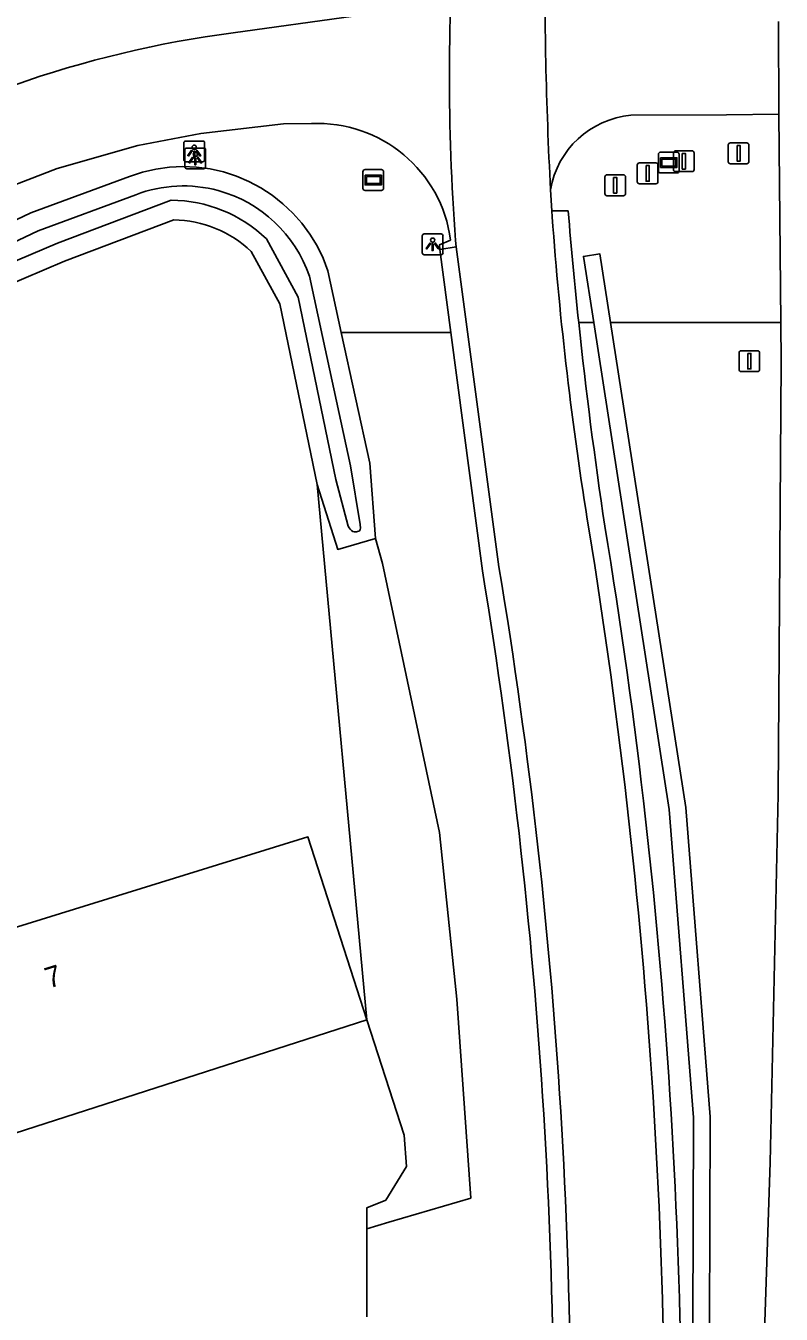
# Model space of a CAD drawing. Extents: x 161389 to 162585, y 388479 to 389761.
# Drawn here: x 162549.2 to 162585.4, y 389564.4 to 389626.2 of the extents above; entities that cross this region are included whole.
import ezdxf

# ---------------------------------------------------------------- set-up
doc = ezdxf.new("R2010")
doc.units = 0
for name, color, linetype in [('IMGEO_Afsluitpaal', 7, 'Continuous'), ('IMGEO_Berm_groen', 7, 'Continuous'), ('IMGEO_Berm_open', 7, 'Continuous'), ('IMGEO_Erf', 7, 'Continuous'), ('IMGEO_Fietspad_gesloten', 7, 'Continuous'), ('IMGEO_Grasland_overig', 7, 'Continuous'), ('IMGEO_Groenvoorziening', 7, 'Continuous'), ('IMGEO_Haag', 7, 'Continuous'), ('IMGEO_Hek', 7, 'Continuous'), ('IMGEO_Lichtpunt', 7, 'Continuous'), ('IMGEO_Pand', 7, 'Continuous'), ('IMGEO_Pand_nummerreeks', 7, 'Continuous'), ('IMGEO_Rijbaan_lokaal_open', 7, 'Continuous'), ('IMGEO_Rijbaan_regionaal_gesloten', 7, 'Continuous'), ('IMGEO_Straatnaambord', 7, 'Continuous'), ('IMGEO_Verkeersbordpaal', 7, 'Continuous'), ('IMGEO_Waterloop', 7, 'Continuous')]:
    doc.layers.add(name, color=color, linetype=linetype)

msp = doc.modelspace()

# ---------------------------------------------------------------- linework, layer by layer
at = {"layer": 'IMGEO_Afsluitpaal'}
for p, q in [((162580.229, 389619.286), (162580.229, 389620.086)), ((162580.229, 389620.086), (162580.229, 389619.286)), ((162580.329, 389620.186), (162581.119, 389620.186)), ((162581.119, 389620.186), (162580.329, 389620.186)), ((162581.219, 389620.086), (162581.219, 389619.286)), ((162581.219, 389619.286), (162581.219, 389620.086)), ((162578.495, 389618.704), (162578.495, 389619.504)), ((162578.495, 389619.504), (162578.495, 389618.704)), ((162578.595, 389619.604), (162579.385, 389619.604)), ((162579.385, 389619.604), (162578.595, 389619.604)), ((162579.485, 389619.504), (162579.485, 389618.704)), ((162579.485, 389618.704), (162579.485, 389619.504)), ((162576.939, 389618.134), (162576.939, 389618.934)), ((162576.939, 389618.934), (162576.939, 389618.134)), ((162577.039, 389619.034), (162577.829, 389619.034)), ((162577.829, 389619.034), (162577.039, 389619.034)), ((162577.929, 389618.934), (162577.929, 389618.134)), ((162577.929, 389618.134), (162577.929, 389618.934)), ((162581.119, 389619.186), (162580.329, 389619.186)), ((162580.329, 389619.186), (162581.119, 389619.186)), ((162579.385, 389618.604), (162578.595, 389618.604)), ((162578.595, 389618.604), (162579.385, 389618.604)), ((162577.829, 389618.034), (162577.039, 389618.034)), ((162577.039, 389618.034), (162577.829, 389618.034))]:
    msp.add_line(p, q, dxfattribs=at)
for points in [[(162580.649, 389620.061), (162580.799, 389620.061), (162580.799, 389619.311), (162580.649, 389619.311), (162580.649, 389620.061)], [(162578.915, 389619.479), (162579.065, 389619.479), (162579.065, 389618.729), (162578.915, 389618.729), (162578.915, 389619.479)], [(162577.359, 389618.909), (162577.509, 389618.909), (162577.509, 389618.159), (162577.359, 389618.159), (162577.359, 389618.909)]]:
    msp.add_lwpolyline(points, dxfattribs=at)
for centre, start, end in [((162580.329, 389620.086), 90, 180), ((162580.329, 389620.086), 90, 180), ((162581.119, 389620.086), 0, 90), ((162581.119, 389620.086), 360, 90), ((162578.595, 389619.504), 90, 180), ((162578.595, 389619.504), 90, 180), ((162579.385, 389619.504), 0, 90), ((162579.385, 389619.504), 360, 90), ((162577.039, 389618.934), 90, 180), ((162577.039, 389618.934), 90, 180), ((162577.829, 389618.934), 0, 90), ((162577.829, 389618.934), 360, 90), ((162580.329, 389619.286), 180, 270), ((162580.329, 389619.286), 180, 270), ((162581.119, 389619.286), 270, 0), ((162581.119, 389619.286), 270, 0), ((162577.039, 389618.134), 180, 270), ((162577.039, 389618.134), 180, 270), ((162577.829, 389618.134), 270, 0), ((162577.829, 389618.134), 270, 0), ((162578.595, 389618.704), 180, 270), ((162578.595, 389618.704), 180, 270), ((162579.385, 389618.704), 270, 0), ((162579.385, 389618.704), 270, 0)]:
    msp.add_arc(centre, 0.1, start, end, dxfattribs=at)
at = {"layer": 'IMGEO_Berm_groen'}
for points in [[(162575.683, 389611.948), (162576.401, 389611.948)], [(162585.381, 389611.948), (162577.211, 389611.948)]]:
    msp.add_lwpolyline(points, dxfattribs=at)
at = {"layer": 'IMGEO_Berm_open'}
for points in [[(162575.179, 389617.305), (162574.394, 389617.306)], [(162569.542, 389611.473), (162569.012, 389615.454)], [(162569.542, 389611.473), (162571.066, 389600.036)]]:
    msp.add_lwpolyline(points, dxfattribs=at)
for centre, radius, start, end in [((162799.629, 389635.72), 225.204, 184.69023, 186.05919), ((162797.305, 389635.461), 222.866, 186.05613, 188.58795), ((162304.581, 389557.197), 276.047, 357.60133, 9.37857), ((162316.554, 389558.165), 257.933, 357.30505, 9.3424)]:
    msp.add_arc(centre, radius, start, end, dxfattribs=at)
at = {"layer": 'IMGEO_Erf'}
for points in [[(162556.26, 389616.875), (162551.015, 389614.89), (162542.21, 389611.153)], [(162563.127, 389604.182), (162561.337, 389612.849), (162559.973, 389615.358)]]:
    msp.add_lwpolyline(points, dxfattribs=at)
msp.add_arc((162556.168, 389611.346), 5.529, 46.51088, 89.04276, dxfattribs=at)
at = {"layer": 'IMGEO_Fietspad_gesloten'}
for points in [[(162574.394, 389617.306), (162574.33, 389618.32)], [(162574.412, 389617.022), (162574.394, 389617.306)], [(162569.81, 389615.58), (162571.853, 389600.234)]]:
    msp.add_lwpolyline(points, dxfattribs=at)
for centre, radius, start, end in [((162741.687, 389629.076), 167.709, 184.1217, 189.27533), ((162298.657, 389556.881), 281.165, 357.71269, 9.24346), ((162320.629, 389558.476), 254.671, 357.21462, 9.43739)]:
    msp.add_arc(centre, radius, start, end, dxfattribs=at)
at = {"layer": 'IMGEO_Grasland_overig'}
for points in [[(162565.517, 389578.496), (162563.127, 389604.182)], [(162563.127, 389604.182), (162564.12, 389601.066), (162565.932, 389601.592)], [(162565.511, 389568.468), (162566.568, 389568.781), (162570.503, 389569.945), (162569.833, 389579.478), (162569.005, 389587.486), (162566.274, 389600.392), (162565.932, 389601.592)], [(162565.511, 389568.468), (162565.512, 389569.468), (162566.425, 389569.847), (162567.427, 389571.463), (162567.301, 389572.963), (162565.517, 389578.496)]]:
    msp.add_lwpolyline(points, dxfattribs=at)
at = {"layer": 'IMGEO_Groenvoorziening'}
for points in [[(162544.825, 389615.043), (162549.393, 389617.208), (162554.136, 389618.956), (162554.76, 389619.16), (162555.397, 389619.307), (162556.044, 389619.396), (162556.696, 389619.427), (162557.349, 389619.4), (162557.996, 389619.315), (162558.634, 389619.172), (162559.256, 389618.972), (162559.857, 389618.718), (162560.434, 389618.412), (162560.981, 389618.054), (162561.494, 389617.65), (162561.968, 389617.201), (162562.401, 389616.712), (162562.788, 389616.186), (162563.127, 389615.627), (162563.414, 389615.041), (162563.648, 389614.431), (162564.291, 389611.473)], [(162564.291, 389611.473), (162569.542, 389611.473)], [(162565.932, 389601.592), (162565.655, 389605.204), (162564.291, 389611.473)], [(162565.509, 389564.253), (162565.511, 389568.468)]]:
    msp.add_lwpolyline(points, dxfattribs=at)
at = {"layer": 'IMGEO_Haag'}
for points in [[(162577.211, 389611.948), (162576.7, 389615.241), (162575.91, 389615.119), (162576.401, 389611.948)], [(162576.401, 389611.948), (162580.024, 389588.585), (162581.189, 389573.807), (162581.108, 389548.906), (162580.883, 389537.221), (162580.277, 389524.986), (162575.533, 389457.902), (162574.175, 389443.824), (162572.862, 389427.679), (162570.704, 389413.369), (162566.096, 389385.679), (162560.933, 389354.655), (162556.805, 389331.01), (162550.72, 389299.239), (162545.517, 389273.568), (162541.107, 389250.072), (162537.047, 389227.348), (162534.227, 389211.564), (162530.189, 389185.447), (162527.69, 389164.49), (162526.335, 389154.682), (162524.353, 389145.747), (162522.076, 389137.161), (162518.583, 389120.758)], [(162566.887, 389385.563), (162571.494, 389413.243), (162573.654, 389427.569), (162574.974, 389443.664), (162576.412, 389457.802), (162581.075, 389524.942), (162581.683, 389537.193), (162581.908, 389548.898), (162581.989, 389573.837), (162580.82, 389588.677), (162577.211, 389611.948)]]:
    msp.add_lwpolyline(points, dxfattribs=at)
at = {"layer": 'IMGEO_Hek'}
msp.add_lwpolyline([(162565.932, 389601.592), (162566.274, 389600.392), (162569.005, 389587.486), (162569.833, 389579.478), (162570.503, 389569.945), (162566.568, 389568.781), (162565.511, 389568.468)], dxfattribs=at)
at = {"layer": 'IMGEO_Lichtpunt'}
for p, q in [((162557.637, 389620.655), (162556.829, 389620.655)), ((162557.637, 389620.655), (162556.829, 389620.655)), ((162556.735, 389620.56), (162556.735, 389619.753)), ((162556.735, 389620.56), (162556.735, 389619.753)), ((162556.785, 389620.224), (162556.785, 389619.417)), ((162556.785, 389620.224), (162556.785, 389619.417)), ((162557.687, 389620.319), (162556.879, 389620.319)), ((162557.687, 389620.319), (162556.879, 389620.319)), ((162557.731, 389619.753), (162557.731, 389620.56)), ((162557.731, 389619.753), (162557.731, 389620.56)), ((162557.781, 389619.417), (162557.781, 389620.224)), ((162557.781, 389619.417), (162557.781, 389620.224)), ((162556.829, 389619.659), (162557.637, 389619.659)), ((162556.829, 389619.659), (162557.637, 389619.659)), ((162556.879, 389619.323), (162557.687, 389619.323)), ((162556.879, 389619.323), (162557.687, 389619.323)), ((162568.175, 389616.104), (162568.175, 389615.297)), ((162568.175, 389616.104), (162568.175, 389615.297)), ((162569.077, 389616.199), (162568.269, 389616.199)), ((162569.077, 389616.199), (162568.269, 389616.199)), ((162569.171, 389615.297), (162569.171, 389616.104)), ((162569.171, 389615.297), (162569.171, 389616.104)), ((162568.269, 389615.203), (162569.077, 389615.203)), ((162568.269, 389615.203), (162569.077, 389615.203))]:
    msp.add_line(p, q, dxfattribs=at)
for points in [[(162557.109, 389620.224), (162557.148, 389620.196), (162556.96, 389619.934), (162556.922, 389619.961), (162557.109, 389620.224)], [(162557.211, 389620.176), (162557.258, 389620.176), (162557.258, 389619.854), (162557.211, 389619.854), (162557.211, 389620.176)], [(162557.321, 389620.196), (162557.359, 389620.223), (162557.546, 389619.961), (162557.507, 389619.933), (162557.321, 389620.196)], [(162557.159, 389619.888), (162557.198, 389619.86), (162557.01, 389619.598), (162556.972, 389619.625), (162557.159, 389619.888)], [(162557.261, 389619.84), (162557.308, 389619.84), (162557.308, 389619.518), (162557.261, 389619.518), (162557.261, 389619.84)], [(162557.371, 389619.86), (162557.409, 389619.887), (162557.596, 389619.625), (162557.557, 389619.597), (162557.371, 389619.86)], [(162568.549, 389615.768), (162568.588, 389615.74), (162568.4, 389615.478), (162568.362, 389615.505), (162568.549, 389615.768)], [(162568.651, 389615.72), (162568.698, 389615.72), (162568.698, 389615.398), (162568.651, 389615.398), (162568.651, 389615.72)], [(162568.761, 389615.74), (162568.799, 389615.767), (162568.986, 389615.505), (162568.947, 389615.477), (162568.761, 389615.74)]]:
    msp.add_lwpolyline(points, dxfattribs=at)
for centre in [(162557.234, 389620.358), (162557.284, 389620.022), (162568.674, 389615.902)]:
    msp.add_circle(centre, 0.0994, dxfattribs=at)
for centre, start, end in [((162556.829, 389620.56), 90, 180), ((162556.829, 389620.56), 90, 180), ((162557.637, 389620.56), 0, 90), ((162557.637, 389620.56), 0, 90), ((162556.879, 389620.224), 90, 180), ((162556.879, 389620.224), 90, 180), ((162557.687, 389620.224), 0, 90), ((162557.687, 389620.224), 0, 90), ((162556.829, 389619.753), 180, 270), ((162556.829, 389619.753), 180, 270), ((162556.879, 389619.417), 180, 270), ((162556.879, 389619.417), 180, 270), ((162557.637, 389619.753), 270, 0), ((162557.637, 389619.753), 270, 360), ((162557.687, 389619.417), 270, 0), ((162557.687, 389619.417), 270, 360), ((162568.269, 389616.104), 90, 180), ((162568.269, 389616.104), 90, 180), ((162569.077, 389616.104), 0, 90), ((162569.077, 389616.104), 0, 90), ((162568.269, 389615.297), 180, 270), ((162568.269, 389615.297), 180, 270), ((162569.077, 389615.297), 270, 0), ((162569.077, 389615.297), 270, 360)]:
    msp.add_arc(centre, 0.0946, start, end, dxfattribs=at)
at = {"layer": 'IMGEO_Pand'}
msp.add_lwpolyline([(162565.517, 389578.496), (162547.191, 389572.588), (162548.561, 389568.331), (162543.802, 389566.8), (162536.446, 389564.434), (162534.742, 389569.151), (162534.484, 389569.057), (162531.437, 389577.419), (162530.514, 389577.136), (162528.223, 389583.678), (162526.571, 389588.397), (162532.896, 389590.432), (162536.408, 389579.136), (162562.687, 389587.272), (162565.517, 389578.496)], dxfattribs=at)
at = {"layer": 'IMGEO_Rijbaan_lokaal_open'}
for points in [[(162564.872, 389626.65), (162559.11, 389625.846)], [(162585.282, 389621.948), (162582.777, 389621.907), (162578.187, 389621.891)], [(162540.808, 389614.65), (162543.297, 389616.119), (162546.908, 389617.892), (162550.663, 389619.336), (162554.532, 389620.438), (162557.552, 389621.024), (162561.524, 389621.473), (162562.854, 389621.493)], [(162569.536, 389615.902), (162569.005, 389615.679), (162569.012, 389615.454)], [(162569.777, 389615.884), (162569.81, 389615.58)], [(162569.012, 389615.454), (162569.81, 389615.58)]]:
    msp.add_lwpolyline(points, dxfattribs=at)
for centre, radius, start, end in [((162673.78, 389623.757), 104.3, 175.42344, 184.32891), ((162779.561, 389628.973), 205.507, 179.55092, 182.97148), ((162565.779, 389574.575), 51.702, 97.41083, 121.50429), ((162578.587, 389617.591), 4.319, 95.31281, 170.27725), ((162563.15, 389615.058), 6.442, 7.52759, 92.63225)]:
    msp.add_arc(centre, radius, start, end, dxfattribs=at)
at = {"layer": 'IMGEO_Rijbaan_regionaal_gesloten'}
for points in [[(162585.265, 389626.39), (162585.282, 389621.948)], [(162585.282, 389621.948), (162585.381, 389611.948)], [(162585.381, 389611.948), (162585.4, 389610.051), (162585.248, 389589.308), (162584.865, 389571.651), (162583.796, 389539.634), (162581.454, 389500), (162580.161, 389481.84), (162577.531, 389457.924), (162576.279, 389443.681), (162572.42, 389412.852), (162568.516, 389385.324)]]:
    msp.add_lwpolyline(points, dxfattribs=at)
at = {"layer": 'IMGEO_Straatnaambord'}
for p, q in [((162579.507, 389619.223), (162579.507, 389620.023)), ((162579.507, 389620.023), (162579.507, 389619.223)), ((162579.607, 389620.123), (162580.397, 389620.123)), ((162580.397, 389620.123), (162579.607, 389620.123)), ((162580.497, 389620.023), (162580.497, 389619.223)), ((162580.497, 389619.223), (162580.497, 389620.023)), ((162565.331, 389618.384), (162565.331, 389619.184)), ((162565.331, 389619.184), (162565.331, 389618.384)), ((162565.431, 389619.284), (162566.221, 389619.284)), ((162566.221, 389619.284), (162565.431, 389619.284)), ((162566.321, 389619.184), (162566.321, 389618.384)), ((162566.321, 389618.384), (162566.321, 389619.184)), ((162580.397, 389619.123), (162579.607, 389619.123)), ((162579.607, 389619.123), (162580.397, 389619.123)), ((162566.221, 389618.284), (162565.431, 389618.284)), ((162565.431, 389618.284), (162566.221, 389618.284))]:
    msp.add_line(p, q, dxfattribs=at)
for points in [[(162579.608, 389619.855), (162580.396, 389619.855), (162580.396, 389619.391), (162579.608, 389619.391), (162579.608, 389619.855)], [(162579.673, 389619.79), (162579.673, 389619.456), (162580.331, 389619.456), (162580.331, 389619.79), (162579.673, 389619.79)], [(162565.432, 389619.016), (162566.22, 389619.016), (162566.22, 389618.552), (162565.432, 389618.552), (162565.432, 389619.016)], [(162565.497, 389618.951), (162565.497, 389618.617), (162566.155, 389618.617), (162566.155, 389618.951), (162565.497, 389618.951)]]:
    msp.add_lwpolyline(points, dxfattribs=at)
for centre, start, end in [((162579.607, 389620.023), 90, 180), ((162579.607, 389620.023), 90, 180), ((162580.397, 389620.023), 0, 90), ((162580.397, 389620.023), 360, 90), ((162565.431, 389619.184), 90, 180), ((162565.431, 389619.184), 90, 180), ((162566.221, 389619.184), 0, 90), ((162566.221, 389619.184), 360, 90), ((162579.607, 389619.223), 180, 270), ((162579.607, 389619.223), 180, 270), ((162580.397, 389619.223), 270, 0), ((162580.397, 389619.223), 270, 0), ((162565.431, 389618.384), 180, 270), ((162565.431, 389618.384), 180, 270), ((162566.221, 389618.384), 270, 0), ((162566.221, 389618.384), 270, 0)]:
    msp.add_arc(centre, 0.1, start, end, dxfattribs=at)
at = {"layer": 'IMGEO_Verkeersbordpaal'}
for p, q in [((162582.96, 389620.565), (162583.75, 389620.565)), ((162583.75, 389620.565), (162582.96, 389620.565)), ((162582.86, 389619.665), (162582.86, 389620.465)), ((162582.86, 389620.465), (162582.86, 389619.665)), ((162583.85, 389620.465), (162583.85, 389619.665)), ((162583.85, 389619.665), (162583.85, 389620.465)), ((162583.75, 389619.565), (162582.96, 389619.565)), ((162582.96, 389619.565), (162583.75, 389619.565)), ((162583.374, 389609.694), (162583.374, 389610.494)), ((162583.374, 389610.494), (162583.374, 389609.694)), ((162583.474, 389610.594), (162584.264, 389610.594)), ((162584.264, 389610.594), (162583.474, 389610.594)), ((162584.364, 389610.494), (162584.364, 389609.694)), ((162584.364, 389609.694), (162584.364, 389610.494)), ((162584.264, 389609.594), (162583.474, 389609.594)), ((162583.474, 389609.594), (162584.264, 389609.594))]:
    msp.add_line(p, q, dxfattribs=at)
for points in [[(162583.28, 389620.44), (162583.43, 389620.44), (162583.43, 389619.69), (162583.28, 389619.69), (162583.28, 389620.44)], [(162583.794, 389610.469), (162583.944, 389610.469), (162583.944, 389609.719), (162583.794, 389609.719), (162583.794, 389610.469)]]:
    msp.add_lwpolyline(points, dxfattribs=at)
for centre, start, end in [((162582.96, 389620.465), 90, 180), ((162582.96, 389620.465), 90, 180), ((162583.75, 389620.465), 0, 90), ((162583.75, 389620.465), 360, 90), ((162582.96, 389619.665), 180, 270), ((162582.96, 389619.665), 180, 270), ((162583.75, 389619.665), 270, 0), ((162583.75, 389619.665), 270, 0), ((162583.474, 389610.494), 90, 180), ((162583.474, 389610.494), 90, 180), ((162584.264, 389610.494), 0, 90), ((162584.264, 389610.494), 360, 90), ((162583.474, 389609.694), 180, 270), ((162583.474, 389609.694), 180, 270), ((162584.264, 389609.694), 270, 0), ((162584.264, 389609.694), 270, 0)]:
    msp.add_arc(centre, 0.1, start, end, dxfattribs=at)
at = {"layer": 'IMGEO_Waterloop'}
for points in [[(162542.564, 389612.602), (162542.645, 389612.71), (162545.256, 389614.223), (162549.752, 389616.354), (162554.44, 389618.082)], [(162556.132, 389617.816), (162550.67, 389615.749), (162542.877, 389612.441)], [(162564.62, 389602.181), (162564.023, 389604.417), (162562.215, 389613.17), (162560.699, 389615.96)], [(162562.759, 389614.166), (162563.387, 389611.276), (162564.737, 389605.07), (162565.197, 389602.257), (162565.21, 389602.084)], [(162565.075, 389601.915), (162565.019, 389601.908), (162564.906, 389601.91), (162564.852, 389601.925)]]:
    msp.add_lwpolyline(points, dxfattribs=at)
for centre, radius, start, end in [((162556.717, 389612.107), 6.394, 74.82129, 110.85868), ((162556.717, 389612.123), 6.378, 18.6778, 74.78052), ((162556.107, 389611.207), 6.609, 45.98658, 89.78039), ((162565.103, 389602.385), 0.524, 202.93609, 241.43279), ((162565.054, 389602.071), 0.157, 277.85511, 4.90801)]:
    msp.add_arc(centre, radius, start, end, dxfattribs=at)

# ---------------------------------------------------------------- texts
at = {"layer": 'IMGEO_Pand_nummerreeks'}
msp.add_text('7', height=1, rotation=17.20257, dxfattribs=at).set_placement((162550.254, 389579.989))

doc.saveas('drawing.dxf')
